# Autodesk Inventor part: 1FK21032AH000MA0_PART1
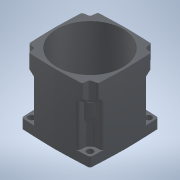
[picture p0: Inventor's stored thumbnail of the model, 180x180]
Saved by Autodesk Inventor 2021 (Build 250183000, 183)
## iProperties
Created: 2025-04
Part Number: 1FK21032AH000MA0_PART1
Material: Generic
Catalog Web Link: www.3dfindit.com
Description: -Servo synchronous motor
Document SubType Name: Modeling
Designer: psAdmin
Mass: 67.0011 g
Surface Area: 303.908 cm^2
Volume: 67.0011 cm^3
Density: 1 g/cm^3
Appearance: PSOLRGB-176-176-176
Category: PARTsolutions
Title: 1FK21032AH000MA0_PART1
Author: Cadenas PARTsolutions
Comments: Servo synchronous motor
Sending System: PARTsolutions
Preprocessor: ST-DEVELOPER v19.3
PSOL_IDENT_0: {$CADENAS_DATA/23d-libs/siemens_ag/_cat_/45/10/1fk21032ah000ma0.prj},213 {VTYP=3D},{NB=1FK21032AH000
PSOL_IDENT_1: MA0_PART1},{LINA=1FK21032AH000MA0_PART1},{NN=1FK21032AH000MA0_PART1},{NOPRJ=TRUE},{DATE=19.08.2025 1
PSOL_IDENT_2: 4:00:35},{GEOMDATE=30.07.2025 02:02:03},{VERSION=},{LINEID=10},{WBVAR=},{WBNUMERIC=}  {NB=1FK21032AH
PSOL_IDENT_3: 000MA0_PART1},{LINA=1FK21032AH000MA0_PART1},{KT=DUMMY},{PREVIEW=../../../_pool_/14/8e/p_d211_xx_0042
PSOL_IDENT_4: 6j.png},{DESCSHORT=SIMOTICS S-1FK2 HD, SINAMICS S210 3AC 400V-480V, 0.59 Nm, 4500 rpm},{DESCLONG=SIM
PSOL_IDENT_5: OTICS S-1FK2 HD servo motor M0=0.64 Nm; PN = 0.28 kW at nN=4500 rpm (380-480 V); PN = 0.167 kW at nN=
PSOL_IDENT_6: 2500 rpm (200-240 V); degree of protection IP64; cylindrical shaft D14 x 30 mm; absolute encoder 22-
PSOL_IDENT_7: bit + 12-bit multiturn (encoder AM22DQC); with OCC interface; plug size M17, rotatable; SIMOTICS S-1
PSOL_IDENT_8: FK2 servomotorfor a wide range of uses in industrial environments. SIMOTICS S‑1FK2 servomotors are c
PSOL_IDENT_9: ompact synchronous motors with a high dynamic performance that set themselves apart as a result of t
PSOL_IDENT_10: heir high power density, degree of protection and overload capability. The motors are available in t
PSOL_IDENT_11: wo variants: as High Dynamic variant (highest dynamic performance as a result of the low intrinsic m
PSOL_IDENT_12: oment of inertia for applications demanding a high dynamic performance with low moved masses) - and
PSOL_IDENT_13: as Compact variant (precise and stable closed-loop control for medium up to large moved masses as a
PSOL_IDENT_14: result of a medium intrinsic moment of inertia). SIMOTICSS‑1FK2 servomotors fully exploit their stre
PSOL_IDENT_15: ngths in a system with the SINAMICSS210 frequency converter and simple connection using the one cabl
PSOL_IDENT_16: e connection (OCC). Advantages include the short control and positioning times, fast and precise cor
PSOL_IDENT_17: rection of disturbing quantities as well as stable control with a high dynamic performance. The serv
PSOL_IDENT_18: o motors can be configured to address a wide range of requirements. For example with and without hol
PSOL_IDENT_19: ding brake, IP64 or IP65 degree of protection, singleturn or multiturn absolute encoders - to name j
PSOL_IDENT_20: ust a few. Further, the servomotors are available in different shaft heights extending from 20 to 10
PSOL_IDENT_21: 0. A shaft sealing ring is available to achieve an IP65 degree of protection and for subsequent moun
PSOL_IDENT_22: ting at the motor or as spare part. SIMOTICS - the optimum motor for each and every motion control a
PSOL_IDENT_23: pplication.},{INTNO=195125335004},{SUPPLIERALTNO=1FK2103-2AH00-0MA0},{MANUID=1FK21032AH000MA0},{MANU
PSOL_IDENT_24: NAME=Siemens},{MANUTYPEDESC=SYNCHRONOUS MOTOR 1FK2 HD 0,64 NM},{AAU732=SIMOTICS},{AAO057=S-1FK2},{AA
PSOL_IDENT_25: U734=SIMOTICS S-1FK2 HD servo motor M0=0.64 Nm; PN = 0.28 kW at nN=4500 rpm (380-480 V); PN = 0.167
PSOL_IDENT_26: kW at nN=2500 rpm (200-240 V); degree of protection IP64; cylindrical shaft D14 x 30 mm; absolute en
PSOL_IDENT_27: coder 22-bit + 12-bit multiturn (encoder AM22DQC); with OCC interface; plug size M17, rotatable;},{A
PSOL_IDENT_28: AW338=SYNCHRONOUS MOTOR 1FK2 HD 0,64 NM},{AAO742=SIMOTICS},{AAO663=4034106444624},{NOCUPEROU=1},{PRI
PSOL_IDENT_29: CEQUANTITY=1},{QUANTITYMIN=1},{QUANTITYINT=1},{CTN=85015100},{COO=RO},{AAO676=1FK2103-2AH00-0MA0},{A
PSOL_IDENT_30: AO677=Siemens AG},{ORDERUNIT=C62},{CONTENTUNIT=C62}
NB: 1FK21032AH000MA0_PART1
NT: Servo synchronous motor
NBSYN: $MANUID._PART1
LINA: 1FK21032AH000MA0_PART1
CATALOG: SIEMENS
PREVIEW: ../../../_pool_/14/8e/p_d211_xx_00426j.png
DESCSHORT: SIMOTICS S-1FK2 HD, SINAMICS S210 3AC 400V-480V, 0.59 Nm, 4500 rpm
DESCLONG: SIMOTICS S-1FK2 HD servo motor M0=0.64 Nm; PN = 0.28 kW at nN=4500 rpm (380-480 V); PN = 0.167 kW at nN=2500 rpm (200-240 V); degree of protection IP64; cylindr
INTNO: 195125335004
SUPPLIERALTNO: 1FK2103-2AH00-0MA0
MANUID: 1FK21032AH000MA0
MANUNAME: Siemens
MANUTYPEDESC: SYNCHRONOUS MOTOR 1FK2 HD 0,64 NM
AAU732: SIMOTICS
AAO057: S-1FK2
AAU734: SIMOTICS S-1FK2 HD servo motor M0=0.64 Nm; PN = 0.28 kW at nN=4500 rpm (380-480 V); PN = 0.167 kW at nN=2500 rpm (200-240 V); degree of protection IP64; cylindr
AAW338: SYNCHRONOUS MOTOR 1FK2 HD 0,64 NM
AAO742: SIMOTICS
AAO663: 4034106444624.0
NOCUPEROU: 1
PRICEQUANTITY: 1
QUANTITYMIN: 1
QUANTITYINT: 1
CTN: 85015100
COO: RO
ARTICLENO: 1FK21032AH000MA0_PART1
BOMINFO: 1FK21032AH000MA0_PART1
CREATOR: CADENAS GmbH
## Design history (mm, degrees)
feature "2025_04_17_15_00_20_0603"
node "ECLASS_CAX_IMPORTER_001_CP_0_XY"
node "ECLASS_CAX_IMPORTER_001_CP_0_YZ"
node "ECLASS_CAX_IMPORTER_001_CP_0_ZX"
node "ECLASS_CAX_IMPORTER_001_CP_0_X"
node "ECLASS_CAX_IMPORTER_001_CP_0_Y"
node "ECLASS_CAX_IMPORTER_001_CP_0_Z"
node "ECLASS_CAX_IMPORTER_001_CP_0_Center"
node "ECLASS_CAX_IMPORTER_001_CP_1_XY"
node "ECLASS_CAX_IMPORTER_001_CP_1_YZ"
node "ECLASS_CAX_IMPORTER_001_CP_1_ZX"
node "ECLASS_CAX_IMPORTER_001_CP_1_X"
node "ECLASS_CAX_IMPORTER_001_CP_1_Y"
node "ECLASS_CAX_IMPORTER_001_CP_1_Z"
node "ECLASS_CAX_IMPORTER_001_CP_1_Center"
body "Solid1"
